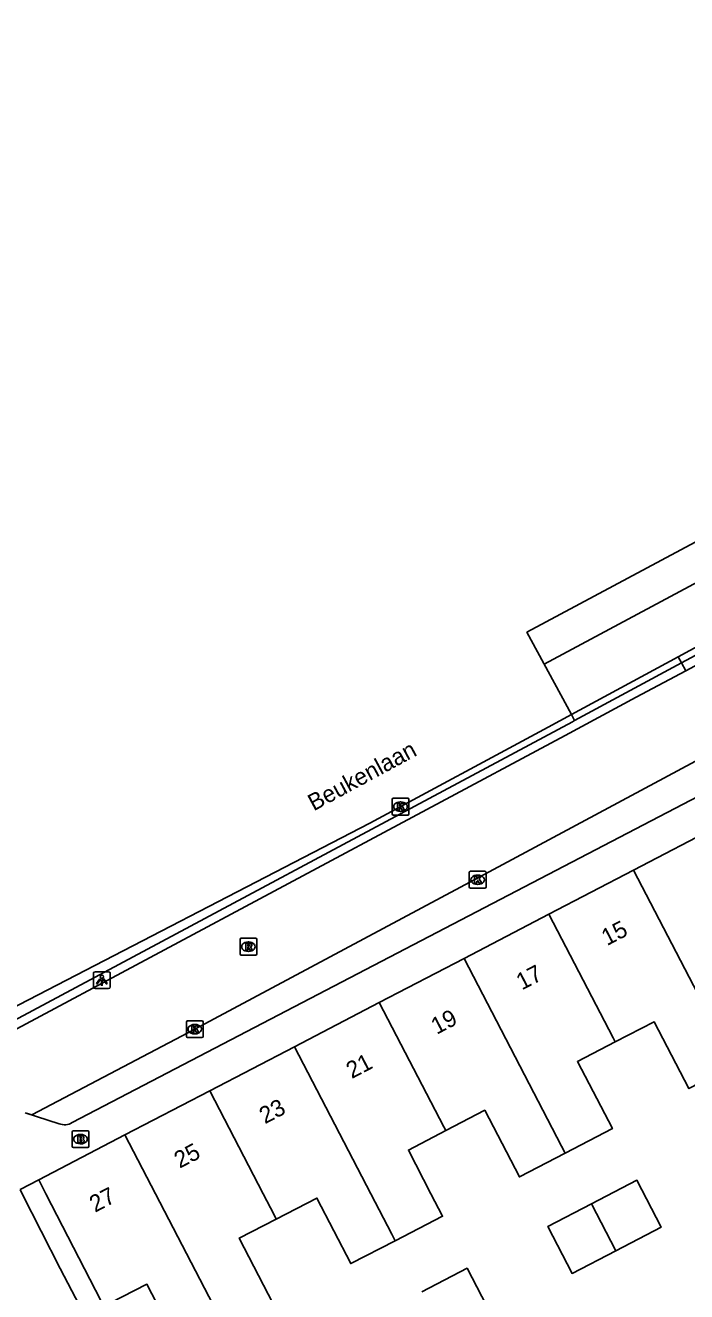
# Model space of a CAD drawing. Extents: x 159265 to 160143, y 383413 to 384319.
# Drawn here: x 159391.1 to 159430.5, y 384244.2 to 384319.4 of the extents above; entities that cross this region are included whole.
import ezdxf

# ---------------------------------------------------------------- set-up
doc = ezdxf.new("R2010")
doc.units = 0
for name, color, linetype in [('IMGEO_Berm_open', 7, 'Continuous'), ('IMGEO_Brandkraan', 7, 'Continuous'), ('IMGEO_Dek', 7, 'Continuous'), ('IMGEO_Kolk', 7, 'Continuous'), ('IMGEO_Lichtpunt', 7, 'Continuous'), ('IMGEO_Openbare_ruimte_label', 7, 'Continuous'), ('IMGEO_Pand', 7, 'Continuous'), ('IMGEO_Pand_nummerreeks', 7, 'Continuous'), ('IMGEO_Parkeervlak_open', 7, 'Continuous'), ('IMGEO_Rijbaan_lokaal_open', 7, 'Continuous'), ('IMGEO_Rijbaan_regionaal_gesloten', 7, 'Continuous'), ('IMGEO_Rioolput', 7, 'Continuous'), ('IMGEO_Voetpad_open', 7, 'Continuous')]:
    doc.layers.add(name, color=color, linetype=linetype)

msp = doc.modelspace()

# ---------------------------------------------------------------- linework, layer by layer
at = {"layer": 'IMGEO_Berm_open'}
msp.add_lwpolyline([(159387.412, 384258.533), (159389.884, 384259.976), (159423.689, 384278.056), (159423.819, 384278.126), (159423.629, 384278.478)], dxfattribs=at)
at = {"layer": 'IMGEO_Brandkraan'}
for p, q in [((159393.93, 384252.823), (159393.93, 384253.675)), ((159394.005, 384253.749), (159394.857, 384253.749)), ((159394.418, 384253.529), (159394.443, 384253.529)), ((159394.931, 384253.675), (159394.931, 384252.823)), ((159394.857, 384252.749), (159394.005, 384252.749)), ((159394.441, 384252.969), (159394.416, 384252.969))]:
    msp.add_line(p, q, dxfattribs=at)
for points in [[(159393.93, 384252.823), (159393.93, 384253.675)], [(159394.005, 384253.749), (159394.857, 384253.749)], [(159394.278, 384253.449), (159394.278, 384253.049), (159394.491, 384253.049)], [(159394.509, 384253.449), (159394.278, 384253.449)], [(159394.457, 384253.368), (159394.403, 384253.368), (159394.403, 384253.292)], [(159394.403, 384253.292), (159394.456, 384253.292)], [(159394.465, 384253.216), (159394.403, 384253.216), (159394.403, 384253.135)], [(159394.403, 384253.135), (159394.465, 384253.135)], [(159394.931, 384253.675), (159394.931, 384252.823)], [(159394.857, 384252.749), (159394.005, 384252.749)]]:
    msp.add_lwpolyline(points, dxfattribs=at)
for centre, radius, start, end in [((159394.007, 384253.673), 0.0765, 91.55205, 178.44795), ((159394.007, 384253.673), 0.0765, 91.55205, 178.44795), ((159394.458, 384253.33), 0.0379, 267.82845, 90.93552), ((159394.466, 384253.175), 0.0404, 269.87594, 90.50774), ((159394.497, 384253.3), 0.251, 268.66757, 293.53466), ((159394.513, 384253.304), 0.145, 59.4692, 91.53667), ((159394.538, 384253.351), 0.0922, 285.51372, 58.15012), ((159394.543, 384253.159), 0.105, 301.31148, 78.98903), ((159394.855, 384253.673), 0.0765, 1.55205, 88.44795), ((159394.855, 384253.673), 0.0765, 1.55205, 88.44795), ((159394.007, 384252.825), 0.0765, 181.55205, 268.44795), ((159394.007, 384252.825), 0.0765, 181.55205, 268.44795), ((159394.855, 384252.825), 0.0765, 271.55205, 358.44795), ((159394.855, 384252.825), 0.0765, 271.55205, 358.44795)]:
    msp.add_arc(centre, radius, start, end, dxfattribs=at)
for centre, major_axis, ratio, start_param, end_param in [((159394.417, 384253.249), (-0.387, 0.002), 0.722429, 4.712389, 7.853982), ((159394.442, 384253.249), (-0.39, 0.002), 0.717154, 1.570796, 4.712389)]:
    msp.add_ellipse(centre, major_axis=major_axis, ratio=ratio, start_param=start_param, end_param=end_param, dxfattribs=at)
at = {"layer": 'IMGEO_Dek'}
msp.add_lwpolyline([(159491.36, 384314.274), (159488.508, 384319.441), (159420.978, 384283.376), (159423.629, 384278.478), (159423.819, 384278.126), (159430.178, 384281.556), (159433.217, 384283.18), (159480.051, 384308.213), (159482.507, 384309.525), (159484.046, 384310.348), (159490.989, 384314.076)], close=True, dxfattribs=at)
at = {"layer": 'IMGEO_Kolk'}
for p, q in [((159412.962, 384272.582), (159412.962, 384273.434)), ((159413.037, 384273.508), (159413.889, 384273.508)), ((159413.963, 384273.434), (159413.963, 384272.582)), ((159413.473, 384272.728), (159413.448, 384272.728)), ((159413.45, 384273.288), (159413.475, 384273.288)), ((159413.889, 384272.508), (159413.037, 384272.508)), ((159417.551, 384268.238), (159417.551, 384269.09)), ((159417.626, 384269.164), (159418.478, 384269.164)), ((159418.039, 384268.944), (159418.064, 384268.944)), ((159418.552, 384269.09), (159418.552, 384268.238)), ((159418.478, 384268.164), (159417.626, 384268.164)), ((159418.062, 384268.384), (159418.037, 384268.384)), ((159400.728, 384259.357), (159400.728, 384260.209)), ((159400.803, 384260.283), (159401.655, 384260.283)), ((159401.216, 384260.063), (159401.241, 384260.063)), ((159401.729, 384260.209), (159401.729, 384259.357)), ((159401.655, 384259.283), (159400.803, 384259.283)), ((159401.239, 384259.503), (159401.214, 384259.503))]:
    msp.add_line(p, q, dxfattribs=at)
for points in [[(159412.962, 384272.582), (159412.962, 384273.434)], [(159413.037, 384273.508), (159413.889, 384273.508)], [(159413.963, 384273.434), (159413.963, 384272.582)], [(159413.283, 384273.208), (159413.406, 384273.208), (159413.406, 384273.057), (159413.536, 384273.208), (159413.7, 384273.208), (159413.554, 384273.057), (159413.707, 384272.808), (159413.555, 384272.808), (159413.47, 384272.972), (159413.406, 384272.905), (159413.406, 384272.808), (159413.283, 384272.808), (159413.283, 384273.208)], [(159413.889, 384272.508), (159413.037, 384272.508)], [(159417.551, 384268.238), (159417.551, 384269.09)], [(159417.626, 384269.164), (159418.478, 384269.164)], [(159417.872, 384268.864), (159417.995, 384268.864), (159417.995, 384268.713), (159418.125, 384268.864), (159418.289, 384268.864), (159418.143, 384268.713), (159418.296, 384268.464), (159418.144, 384268.464), (159418.059, 384268.628), (159417.995, 384268.561), (159417.995, 384268.464), (159417.872, 384268.464), (159417.872, 384268.864)], [(159418.552, 384269.09), (159418.552, 384268.238)], [(159418.478, 384268.164), (159417.626, 384268.164)], [(159400.728, 384259.357), (159400.728, 384260.209)], [(159400.803, 384260.283), (159401.655, 384260.283)], [(159401.049, 384259.983), (159401.172, 384259.983), (159401.172, 384259.832), (159401.302, 384259.983), (159401.466, 384259.983), (159401.32, 384259.832), (159401.473, 384259.583), (159401.321, 384259.583), (159401.236, 384259.747), (159401.172, 384259.68), (159401.172, 384259.583), (159401.049, 384259.583), (159401.049, 384259.983)], [(159401.729, 384260.209), (159401.729, 384259.357)], [(159401.655, 384259.283), (159400.803, 384259.283)]]:
    msp.add_lwpolyline(points, dxfattribs=at)
for centre, start, end in [((159413.039, 384273.432), 91.55205, 178.44795), ((159413.039, 384273.432), 91.55205, 178.44795), ((159413.887, 384273.432), 1.55205, 88.44795), ((159413.887, 384273.432), 1.55205, 88.44795), ((159413.039, 384272.584), 181.55205, 268.44795), ((159413.039, 384272.584), 181.55205, 268.44795), ((159413.887, 384272.584), 271.55205, 358.44795), ((159413.887, 384272.584), 271.55205, 358.44795), ((159417.628, 384269.088), 91.55205, 178.44795), ((159417.628, 384269.088), 91.55205, 178.44795), ((159418.476, 384269.088), 1.55205, 88.44795), ((159418.476, 384269.088), 1.55205, 88.44795), ((159417.628, 384268.24), 181.55205, 268.44795), ((159417.628, 384268.24), 181.55205, 268.44795), ((159418.476, 384268.24), 271.55205, 358.44795), ((159418.476, 384268.24), 271.55205, 358.44795), ((159400.805, 384260.207), 91.55205, 178.44795), ((159400.805, 384260.207), 91.55205, 178.44795), ((159401.653, 384260.207), 1.55205, 88.44795), ((159401.653, 384260.207), 1.55205, 88.44795), ((159400.805, 384259.359), 181.55205, 268.44795), ((159400.805, 384259.359), 181.55205, 268.44795), ((159401.653, 384259.359), 271.55205, 358.44795), ((159401.653, 384259.359), 271.55205, 358.44795)]:
    msp.add_arc(centre, 0.0765, start, end, dxfattribs=at)
for centre, major_axis, ratio, start_param, end_param in [((159413.449, 384273.008), (-0.387, 0.002), 0.722429, 4.712389, 7.853982), ((159413.474, 384273.008), (-0.39, 0.002), 0.717154, 1.570796, 4.712389), ((159418.038, 384268.664), (-0.387, 0.002), 0.722429, 4.712389, 7.853982), ((159418.063, 384268.664), (-0.39, 0.002), 0.717154, 1.570796, 4.712389), ((159401.215, 384259.783), (-0.387, 0.002), 0.722429, 4.712389, 7.853982), ((159401.24, 384259.783), (-0.39, 0.002), 0.717154, 1.570796, 4.712389)]:
    msp.add_ellipse(centre, major_axis=major_axis, ratio=ratio, start_param=start_param, end_param=end_param, dxfattribs=at)
at = {"layer": 'IMGEO_Lichtpunt'}
for p, q in [((159395.202, 384263.103), (159395.202, 384262.296)), ((159395.202, 384263.103), (159395.202, 384262.296)), ((159396.104, 384263.198), (159395.296, 384263.198)), ((159396.104, 384263.198), (159395.296, 384263.198)), ((159396.198, 384262.296), (159396.198, 384263.103)), ((159396.198, 384262.296), (159396.198, 384263.103)), ((159395.296, 384262.202), (159396.104, 384262.202)), ((159395.296, 384262.202), (159396.104, 384262.202))]:
    msp.add_line(p, q, dxfattribs=at)
for points in [[(159395.576, 384262.767), (159395.615, 384262.739), (159395.427, 384262.477), (159395.389, 384262.504), (159395.576, 384262.767)], [(159395.678, 384262.719), (159395.725, 384262.719), (159395.725, 384262.397), (159395.678, 384262.397), (159395.678, 384262.719)], [(159395.788, 384262.739), (159395.826, 384262.766), (159396.013, 384262.504), (159395.974, 384262.476), (159395.788, 384262.739)]]:
    msp.add_lwpolyline(points, dxfattribs=at)
msp.add_circle((159395.701, 384262.901), 0.0994, dxfattribs=at)
for centre, start, end in [((159395.296, 384263.103), 90, 180), ((159395.296, 384263.103), 90, 180), ((159396.104, 384263.103), 0, 90), ((159396.104, 384263.103), 0, 90), ((159395.296, 384262.296), 180, 270), ((159395.296, 384262.296), 180, 270), ((159396.104, 384262.296), 270, 0), ((159396.104, 384262.296), 270, 360)]:
    msp.add_arc(centre, 0.0946, start, end, dxfattribs=at)
at = {"layer": 'IMGEO_Pand'}
for points in [[(159427.328, 384269.238), (159432.484, 384271.922)], [(159422.285, 384266.614), (159427.328, 384269.238)], [(159433.339, 384257.673), (159433.165, 384258.008), (159427.328, 384269.238)], [(159417.244, 384263.99), (159422.285, 384266.614)], [(159422.285, 384266.614), (159426.104, 384259.267), (159426.23, 384259.025)], [(159412.201, 384261.366), (159417.244, 384263.99)], [(159423.26, 384252.415), (159423.047, 384252.825), (159417.244, 384263.99)], [(159407.159, 384258.742), (159412.201, 384261.366)], [(159416.155, 384253.757), (159416.043, 384253.974), (159412.201, 384261.366)], [(159426.23, 384259.025), (159428.546, 384260.229), (159430.611, 384256.255), (159433.339, 384257.673)], [(159402.116, 384256.117), (159407.159, 384258.742)], [(159413.151, 384247.213), (159412.949, 384247.601), (159411.702, 384250), (159407.159, 384258.742)], [(159423.26, 384252.415), (159426.061, 384253.871), (159423.988, 384257.86), (159426.23, 384259.025)], [(159397.074, 384253.494), (159402.116, 384256.117)], [(159402.116, 384256.117), (159405.296, 384250), (159405.951, 384248.74), (159406.076, 384248.5)], [(159416.155, 384253.757), (159418.476, 384254.964), (159420.536, 384250.999), (159423.26, 384252.415)], [(159391.947, 384250.825), (159397.074, 384253.494)], [(159403.053, 384241.99), (159402.858, 384242.366), (159398.89, 384250), (159397.074, 384253.494)], [(159413.151, 384247.213), (159415.968, 384248.664), (159415.276, 384250), (159413.929, 384252.6), (159416.155, 384253.757)], [(159391.947, 384250.825), (159392.372, 384250), (159395.969, 384243.009), (159396.322, 384243.219), (159396.182, 384243.491), (159398.382, 384244.625), (159400.435, 384240.641), (159403.053, 384241.99)], [(159426.273, 384246.618), (159428.967, 384248.017), (159427.521, 384250.801), (159424.826, 384249.401)], [(159390.768, 384238.692), (159393.102, 384234.267), (159397.827, 384236.735), (159395.511, 384241.169), (159393.22, 384245.555), (159390.963, 384250), (159390.833, 384250.255)], [(159406.076, 384248.5), (159408.496, 384249.747), (159410.504, 384245.849), (159413.151, 384247.213)], [(159424.826, 384249.401), (159422.224, 384248.05), (159423.67, 384245.266), (159426.273, 384246.618)], [(159424.826, 384249.401), (159426.273, 384246.618)], [(159403.053, 384241.99), (159405.892, 384243.452), (159403.876, 384247.366), (159406.076, 384248.5)], [(159416.175, 384241.394), (159418.869, 384242.793), (159417.423, 384245.577), (159414.729, 384244.178)]]:
    msp.add_lwpolyline(points, dxfattribs=at)
at = {"layer": 'IMGEO_Parkeervlak_open'}
msp.add_lwpolyline([(159423.629, 384278.478), (159429.983, 384281.917), (159430.178, 384281.556), (159430.427, 384281.088)], dxfattribs=at)
at = {"layer": 'IMGEO_Rijbaan_lokaal_open'}
for points in [[(159475.396, 384299.461), (159462.736, 384292.692), (159450.164, 384285.967), (159418.184, 384268.831), (159401.228, 384259.783), (159391.541, 384254.692), (159391.148, 384254.814)], [(159430.427, 384281.088), (159433.002, 384282.456)], [(159387.644, 384258.15), (159390.341, 384259.651), (159423.246, 384277.236), (159427.486, 384279.521), (159430.427, 384281.088)]]:
    msp.add_lwpolyline(points, dxfattribs=at)
at = {"layer": 'IMGEO_Rijbaan_regionaal_gesloten'}
for points in [[(159489.531, 384317.589), (159488.719, 384317.155), (159474.585, 384309.589), (159460.499, 384302.052), (159446.472, 384294.563), (159422.005, 384281.479)], [(159423.629, 384278.478), (159429.983, 384281.917), (159433.442, 384283.79), (159435.406, 384284.854), (159448.468, 384291.784), (159464.216, 384300.192), (159479.855, 384308.569), (159480.117, 384308.71), (159481.376, 384309.31), (159482.698, 384310.074), (159483.205, 384310.367), (159484.438, 384311.028), (159490.788, 384314.434), (159491.161, 384314.634)], [(159423.629, 384278.478), (159420.978, 384283.376)], [(159360.8, 384243.819), (159363.349, 384245.322), (159371.368, 384250), (159380.122, 384255.107), (159388.083, 384259.739), (159389.631, 384260.66), (159411.634, 384272.028), (159422.254, 384277.734), (159423.629, 384278.478)]]:
    msp.add_lwpolyline(points, dxfattribs=at)
at = {"layer": 'IMGEO_Rioolput'}
for p, q in [((159403.919, 384264.259), (159403.919, 384265.111)), ((159403.994, 384265.185), (159404.846, 384265.185)), ((159404.92, 384265.111), (159404.92, 384264.259)), ((159404.43, 384264.405), (159404.405, 384264.405)), ((159404.407, 384264.965), (159404.432, 384264.965)), ((159404.846, 384264.185), (159403.994, 384264.185))]:
    msp.add_line(p, q, dxfattribs=at)
for points in [[(159403.919, 384264.259), (159403.919, 384265.111)], [(159403.994, 384265.185), (159404.846, 384265.185)], [(159404.92, 384265.111), (159404.92, 384264.259)], [(159404.508, 384264.883), (159404.256, 384264.885), (159404.256, 384264.485)], [(159404.256, 384264.485), (159404.38, 384264.485), (159404.38, 384264.647), (159404.391, 384264.647)], [(159404.434, 384264.804), (159404.38, 384264.804), (159404.38, 384264.723)], [(159404.38, 384264.723), (159404.432, 384264.723)], [(159404.438, 384264.618), (159404.509, 384264.485), (159404.649, 384264.485), (159404.584, 384264.611)], [(159404.846, 384264.185), (159403.994, 384264.185)]]:
    msp.add_lwpolyline(points, dxfattribs=at)
for centre, radius, start, end in [((159403.996, 384265.109), 0.0765, 91.55205, 178.44795), ((159403.996, 384265.109), 0.0765, 91.55205, 178.44795), ((159404.844, 384265.109), 0.0765, 1.55205, 88.44795), ((159404.844, 384265.109), 0.0765, 1.55205, 88.44795), ((159404.39, 384264.594), 0.0533, 26.02933, 88.69889), ((159404.416, 384264.912), 0.19, 274.7715, 282.96867), ((159404.44, 384264.708), 0.0964, 77.00612, 93.18647), ((159404.454, 384264.765), 0.0378, 276.66336, 79.67722), ((159404.507, 384264.773), 0.109, 350.36119, 89.41601), ((159404.505, 384264.773), 0.112, 277.58423, 350.98172), ((159404.489, 384264.558), 0.108, 29.51342, 73.79051), ((159403.996, 384264.261), 0.0765, 181.55205, 268.44795), ((159403.996, 384264.261), 0.0765, 181.55205, 268.44795), ((159404.844, 384264.261), 0.0765, 271.55205, 358.44795), ((159404.844, 384264.261), 0.0765, 271.55205, 358.44795)]:
    msp.add_arc(centre, radius, start, end, dxfattribs=at)
for centre, major_axis, ratio, start_param, end_param in [((159404.406, 384264.685), (-0.387, 0.002), 0.722429, 4.712389, 7.853982), ((159404.431, 384264.685), (-0.39, 0.002), 0.717154, 1.570796, 4.712389)]:
    msp.add_ellipse(centre, major_axis=major_axis, ratio=ratio, start_param=start_param, end_param=end_param, dxfattribs=at)
at = {"layer": 'IMGEO_Voetpad_open'}
for points in [[(159393.93, 384254.235), (159435.444, 384275.844), (159435.072, 384276.504)], [(159391.148, 384254.814), (159393.158, 384254.165)], [(159390.833, 384250.255), (159391.947, 384250.825)]]:
    msp.add_lwpolyline(points, dxfattribs=at)
msp.add_arc((159393.477, 384254.936), 0.835, 247.51831, 302.84378, dxfattribs=at)

# ---------------------------------------------------------------- texts
at = {"layer": 'IMGEO_Openbare_ruimte_label'}
msp.add_text('Beukenlaan', height=1, rotation=28.40936, dxfattribs=at).set_placement((159408.302, 384272.724))
at = {"layer": 'IMGEO_Pand_nummerreeks'}
for s, rotation, p in [('15', 27.49419, (159425.745, 384264.717)), ('17', 27.49419, (159420.678, 384262.08)), ('19', 27.49419, (159415.611, 384259.443)), ('21', 27.49419, (159410.564, 384256.816)), ('23', 27.49419, (159405.397, 384254.126)), ('25', 27.49419, (159400.329, 384251.489)), ('27', 27.50046, (159395.294, 384248.869))]:
    msp.add_text(s, height=1, rotation=rotation, dxfattribs=at).set_placement(p)

doc.saveas('drawing.dxf')
